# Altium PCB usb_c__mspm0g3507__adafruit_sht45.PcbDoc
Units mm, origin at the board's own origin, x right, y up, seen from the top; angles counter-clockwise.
Board outline 92 x 60 mm, 2 copper layers (Top, Bottom), stack 0 mm thick; 37 components, 33 nets, 186 pads, 47 vias.
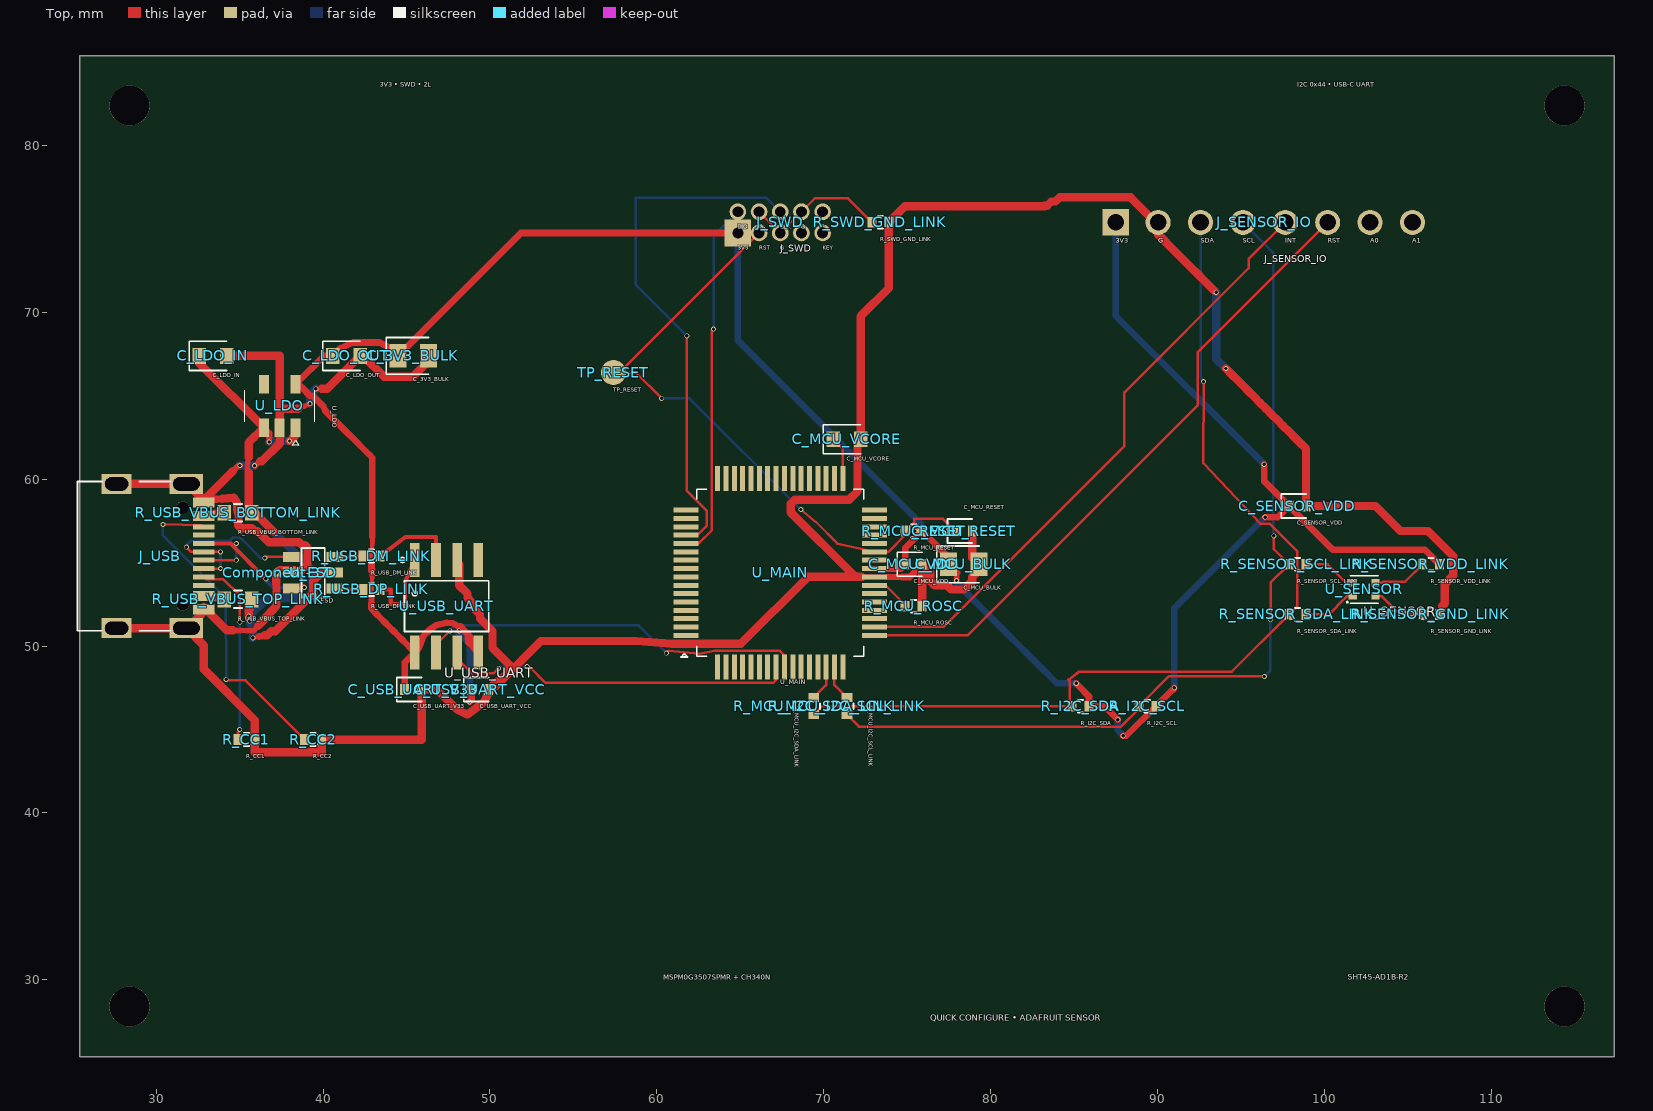
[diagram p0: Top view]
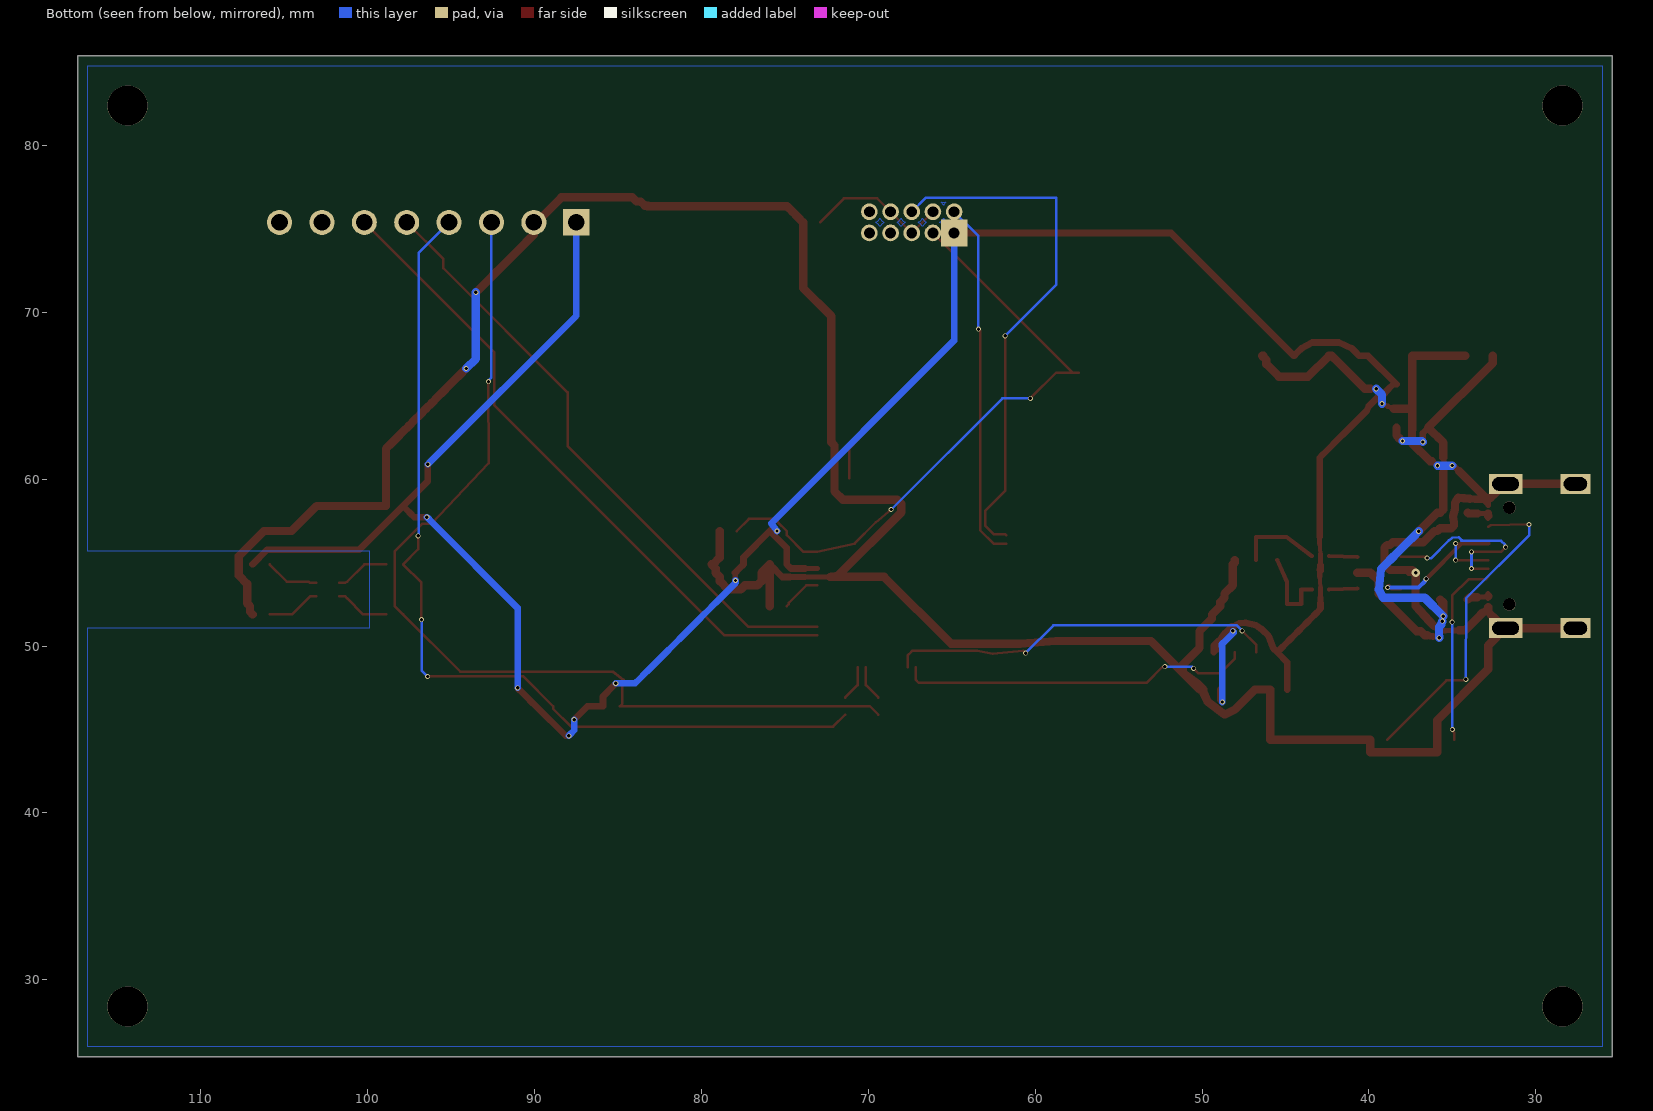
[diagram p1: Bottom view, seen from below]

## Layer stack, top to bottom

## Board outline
25.4,85.4 117.4,85.4 117.4,25.4 25.4,25.4

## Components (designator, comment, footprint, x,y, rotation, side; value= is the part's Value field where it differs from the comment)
C_3V3_BULK "" TSCIRCUIT-2.8500x1.4000mm 45.4,67.4 r0 top
C_LDO_IN "" TSCIRCUIT-2.4500x0.9500mm 33.4,67.4 r0 top
C_LDO_OUT "" TSCIRCUIT-2.4500x0.9500mm 41.4,67.4 r0 top
C_MCU_BULK "" TSCIRCUIT-2.8500x1.4000mm 78.4,54.9 r0 top
C_MCU_RESET "" TSCIRCUIT-1.5600x0.6400mm 78.4,56.9 r0 top
C_MCU_VCORE "" TSCIRCUIT-2.4500x0.9500mm 71.4,62.4 r0 top
C_MCU_VDD "" TSCIRCUIT-1.5600x0.6400mm 75.4,54.9 r0 top
C_SENSOR_VDD "" TSCIRCUIT-1.5600x0.6400mm 98.4,58.4 r0 top
C_USB_UART_V33 "" TSCIRCUIT-1.5600x0.6400mm 45.4,47.4 r0 top
C_USB_UART_VCC "" TSCIRCUIT-1.5600x0.6400mm 49.4,47.4 r0 top
Component-37 "" TSCIRCUIT-0.5000x0.5000mm 37.2,54.4 r0 top
J_SENSOR_IO "" TSCIRCUIT-19.2800x1.5000mm 96.4,75.4 r0 top
J_SWD "" TSCIRCUIT-6.0800x2.2700mm 67.4,75.4 r0 top
J_USB "" TSCIRCUIT-6.7732x9.8502mm 30.113,55.4 r90 top
R_CC1 "" TSCIRCUIT-1.5600x0.6400mm 35.4,44.4 r0 top
R_CC2 "" TSCIRCUIT-1.5600x0.6400mm 39.4,44.4 r0 top
R_I2C_SCL "" TSCIRCUIT-1.5600x0.6400mm 89.4,46.4 r0 top
R_I2C_SDA "" TSCIRCUIT-1.5600x0.6400mm 85.4,46.4 r0 top
R_MCU_I2C_SCL_LINK "" TSCIRCUIT-0.6400x1.5600mm 71.4,46.4 r270 top
R_MCU_I2C_SDA_LINK "" TSCIRCUIT-0.6400x1.5600mm 69.4,46.4 r270 top
R_MCU_RESET "" TSCIRCUIT-1.5600x0.6400mm 75.4,56.9 r0 top
R_MCU_ROSC "" TSCIRCUIT-1.5600x0.6400mm 75.4,52.4 r0 top
R_SENSOR_GND_LINK "" TSCIRCUIT-1.5600x0.6400mm 106.4,51.9 r0 top
R_SENSOR_SCL_LINK "" TSCIRCUIT-1.5600x0.6400mm 98.4,54.9 r0 top
R_SENSOR_SDA_LINK "" TSCIRCUIT-1.5600x0.6400mm 98.4,51.9 r0 top
R_SENSOR_VDD_LINK "" TSCIRCUIT-1.5600x0.6400mm 106.4,54.9 r0 top
R_SWD_GND_LINK "" TSCIRCUIT-1.5600x0.6400mm 73.4,75.4 r0 top
R_USB_DM_LINK "" TSCIRCUIT-1.5600x0.6400mm 42.9,55.4 r0 top
R_USB_DP_LINK "" TSCIRCUIT-1.5600x0.6400mm 42.9,53.4 r0 top
R_USB_VBUS_BOTTOM_LINK "" TSCIRCUIT-2.4500x0.9500mm 34.9,58 r0 top
R_USB_VBUS_TOP_LINK "" TSCIRCUIT-2.4500x0.9500mm 34.9,52.8 r0 top
TP_RESET "" TSCIRCUIT-1.5000x1.5000mm 57.4,66.4 r0 top
U_ESD "" TSCIRCUIT-3.6000x2.5000mm 39.4,54.4 r0 top
U_LDO "" TSCIRCUIT-2.5000x3.7000mm 37.4,64.4 r270 top
U_MAIN "" TSCIRCUIT-12.8000x12.8000mm 67.4,54.4 r0 top
U_SENSOR "" TSCIRCUIT-1.8598x1.2201mm 102.4,53.4 r0 top
U_USB_UART "" TSCIRCUIT-4.3840x7.5712mm 47.4,52.4 r0 top

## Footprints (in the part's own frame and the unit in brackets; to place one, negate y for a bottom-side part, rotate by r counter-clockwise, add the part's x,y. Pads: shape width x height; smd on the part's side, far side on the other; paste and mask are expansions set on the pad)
TSCIRCUIT-0.5000x0.5000mm [mm]
TSCIRCUIT-0.6400x1.5600mm [mm]
  rect 0.54x0.64 smd: 1(-0.51,0) 2(0.51,0)
  silkscreen extent -0.15,-0.38 0.15,0.38
TSCIRCUIT-1.5000x1.5000mm [mm]
  round 1.5 smd: 1(0,0)
TSCIRCUIT-1.5600x0.6400mm [mm]
  rect 0.54x0.64 smd: 1(-0.51,0) 2(0.51,0)
  silkscreen extent -0.98,-0.72 0.51,0.72
TSCIRCUIT-1.8598x1.2201mm [mm]
  rect 0.505x0.42 smd: 1(-0.677,-0.4) 2(-0.677,0.4) 3(0.677,0.4) 4(0.677,-0.4)
  silkscreen extent -1.05,-0.83 0.83,0.83
TSCIRCUIT-2.4500x0.9500mm [mm]
  rect 0.8x0.95 smd: 1(-0.825,0) 2(0.825,0)
  silkscreen extent -1.42,-0.87 0.82,0.87
TSCIRCUIT-2.5000x3.7000mm [mm]
  rect 1.1x0.6 smd: 1(1.3,0.95) 2(1.3,0) 3(1.3,-0.95) 4(-1.3,-0.95) 5(-1.3,0.95)
  silkscreen extent -0.95,-2.1 2.35,2.1
TSCIRCUIT-2.8500x1.4000mm [mm]
  rect 1.025x1.4 smd: 1(-0.913,0) 2(0.913,0)
  silkscreen extent -1.63,-1.1 0.91,1.1
TSCIRCUIT-3.6000x2.5000mm [mm]
  rect 1x0.6 smd: 1(-1.3,-0.95) 2(-1.3,0) 3(-1.3,0.95) 4(1.3,0.95) 5(1.3,0) 6(1.3,-0.95)
  silkscreen extent -0.7,-1.49 0.7,1.49
TSCIRCUIT-4.3840x7.5712mm [mm]
  rect 0.574x2.036 smd: 1(-1.905,2.768) 2(-0.635,2.768) 3(0.635,2.768) 4(1.905,2.768) 5(1.905,-2.768) 6(0.635,-2.768) 7(-0.635,-2.768) 8(-1.905,-2.768)
  silkscreen extent -2.79,-1.52 2.53,2.92
TSCIRCUIT-6.0800x2.2700mm [mm]
  rect 1.6x1.6 hole 0.65: 1(-2.54,-0.635)
  round 1 hole 0.65: 2(-2.54,0.635) 3(-1.27,0.635) 4(0,0.635) 5(1.27,0.635) 6(2.54,0.635) 7(2.54,-0.635) 8(1.27,-0.635) 9(0,-0.635) 10(-1.27,-0.635)
TSCIRCUIT-6.7732x9.8502mm [mm]
  rect 0.3x1.3 smd: 1(-3.35,-2.737) 2(-3.05,-2.737) 3(-2.55,-2.737) 4(-2.25,-2.737) 5(-1.75,-2.737) 6(-1.25,-2.737) 7(-0.75,-2.737) 8(-0.25,-2.737) 9(0.25,-2.737) 10(0.75,-2.737) 11(1.25,-2.737) 12(1.75,-2.737) 13(2.55,-2.737) 14(2.25,-2.737) 15(3.35,-2.737) 16(3.05,-2.737)
  rect 1.2x2 hole 0.8 slot 1.6 at 90 deg: 17(-4.325,-1.693) 18(4.325,-1.693)
  rect 1.2x1.8 hole 0.8 slot 1.4 at 90 deg: 19(4.325,2.487) 20(-4.325,2.487)
  round 0.75 hole 0.75 unplated: NPTH-1(-2.9,-1.468) NPTH-2(2.9,-1.468)
  silkscreen extent -4.47,-0.75 4.47,4.83
TSCIRCUIT-12.8000x12.8000mm [mm]
  rect 1.5x0.3 smd: 1(-5.65,-3.75) 2(-5.65,-3.25) 3(-5.65,-2.75) 4(-5.65,-2.25) 5(-5.65,-1.75) 6(-5.65,-1.25) 7(-5.65,-0.75) 8(-5.65,-0.25) 9(-5.65,0.25) 10(-5.65,0.75) 11(-5.65,1.25) 12(-5.65,1.75) 13(-5.65,2.25) 14(-5.65,2.75) 15(-5.65,3.25) 16(-5.65,3.75) 33(5.65,3.75) 34(5.65,3.25) 35(5.65,2.75) 36(5.65,2.25) 37(5.65,1.75) 38(5.65,1.25) 39(5.65,0.75) 40(5.65,0.25) 41(5.65,-0.25) 42(5.65,-0.75) 43(5.65,-1.25) 44(5.65,-1.75) 45(5.65,-2.25) 46(5.65,-2.75) 47(5.65,-3.25) 48(5.65,-3.75)
  rect 0.3x1.5 smd: 17(-3.75,5.65) 18(-3.25,5.65) 19(-2.75,5.65) 20(-2.25,5.65) 21(-1.75,5.65) 22(-1.25,5.65) 23(-0.75,5.65) 24(-0.25,5.65) 25(0.25,5.65) 26(0.75,5.65) 27(1.25,5.65) 28(1.75,5.65) 29(2.25,5.65) 30(2.75,5.65) 31(3.25,5.65) 32(3.75,5.65) 49(3.75,-5.65) 50(3.25,-5.65) 51(2.75,-5.65) 52(2.25,-5.65) 53(1.75,-5.65) 54(1.25,-5.65) 55(0.75,-5.65) 56(0.25,-5.65) 57(-0.25,-5.65) 58(-0.75,-5.65) 59(-1.25,-5.65) 60(-1.75,-5.65) 61(-2.25,-5.65) 62(-2.75,-5.65) 63(-3.25,-5.65) 64(-3.75,-5.65)
  silkscreen extent -5.95,-5.05 5,5
TSCIRCUIT-19.2800x1.5000mm [mm]
  rect 1.6x1.6 hole 1: 1(-8.89,0)
  round 1.5 hole 1: 2(-6.35,0) 3(-3.81,0) 4(-1.27,0) 5(1.27,0) 6(3.81,0) 7(6.35,0) 8(8.89,0)

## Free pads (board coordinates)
  round 2.4 hole 2.4 unplated: NPTH-3(28.4,28.4) NPTH-4(114.4,28.4) NPTH-5(28.4,82.4) NPTH-6(114.4,82.4)

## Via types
v1: diameter 0.3, hole 0.2, Top to Bottom, 46 vias
v2: diameter 0.5, hole 0.2, Top to Bottom, 1 vias

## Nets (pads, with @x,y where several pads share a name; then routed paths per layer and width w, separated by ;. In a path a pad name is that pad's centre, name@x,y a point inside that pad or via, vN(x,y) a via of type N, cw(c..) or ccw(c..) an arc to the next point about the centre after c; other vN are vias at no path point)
".J_SWD > .pin2 to .U_MAIN > .pin12": J_SWD.2 U_MAIN.12 | length 21.6
  Top w0.15: U_MAIN.12 62.499,56.15 63.298,56.949 63.298,59.12 63.298,68.898 v1(63.4,69)
  Bottom w0.15: v1(63.4,69) 63.4,69.14 63.4,74.575 J_SWD.2
".J_SWD > .pin4 to .U_MAIN > .pin13": J_SWD.4 U_MAIN.13 | length 31.9
  Top w0.15: U_MAIN.13 61.811,56.711 62.49,56.711 63.008,57.229 63.008,58.102 61.8,59.31 v1(61.8,68.6)
  Bottom w0.15: v1(61.8,68.6) 61.756,68.644 58.745,71.655 58.745,76.868 66.567,76.868 J_SWD.4
".U_MAIN > .pin42 to .R_MCU_ROSC > .pin1": R_MCU_ROSC.1 U_MAIN.42 | length 2.4
  Top w0.15: U_MAIN.42 73.719,53.65 74.769,52.6 74.769,52.521 R_MCU_ROSC.1
GND: C_3V3_BULK.2 C_LDO_IN.2 C_LDO_OUT.2 C_MCU_BULK.2 C_MCU_RESET.2 C_MCU_VCORE.2 C_MCU_VDD.2 C_SENSOR_VDD.2 C_USB_UART_V33.2 C_USB_UART_VCC.2 J_SENSOR_IO.2 J_USB.1 J_USB.2 J_USB.15 J_USB.16 J_USB.17 J_USB.18 J_USB.19 J_USB.20 R_CC1.2 R_CC2.2 R_MCU_ROSC.2 R_SENSOR_GND_LINK.2 R_SWD_GND_LINK.2 U_ESD.2 U_LDO.2 U_MAIN.41 U_USB_UART.3 | length 216.2
  Top w0.275: J_USB.16 J_USB.15@33.202,58.803
  Top w0.3: J_USB.1@32.699,51.9 J_USB.1 J_USB.1@32.849,52.2 ; J_USB.15@32.699,58.9 J_USB.15 ; J_USB.2 J_USB.1@32.995,52.2 ; J_USB.16@32.849,58.6 J_USB.15 ; J_USB.15@32.999,58.9 J_USB.15 ; v1(39.568,65.421) 39.907,65.421 ; U_MAIN.41@73.8,54.15 73.706,54.15 73.612,54.15 73.519,54.15 73.425,54.15 73.331,54.15 73.237,54.15 73.144,54.15 U_MAIN.41 ; U_MAIN.41 72.627,54.15 72.3,54.15 72.55,54.15 U_MAIN.41
  Top w0.312: 38.513,64.225 38.866,64.38 v1(39.219,64.535)
  Top w0.325: J_USB.16 J_USB.16@32.849,58.6 ; J_USB.1@32.994,52.2 J_USB.1@33.186,52.003 ; 35.01,50.936 35.417,50.923 35.823,50.911 36.1,51.21 ; v1(35.89,60.817) 35.911,60.796 v1@35.913,60.796
  Top w0.35: v1@35.913,60.796 36.216,61.092 ; 93.416,71.317 v1(93.528,71.205)
  Top w0.375: 34.578,60.479 34.924,60.825 v1(35.007,60.825) ; 34.603,50.948 35.01,50.936 ; U_MAIN.41@73.8,54.15 74.253,54.15 74.707,54.15
  Top w0.4: 37.2,54.4 U_ESD.2@37.6,54.4 ; 74.707,54.15 75.16,54.15 75.41,54.4 75.66,54.65 C_MCU_VDD.2
  Top w0.45: J_USB.15@33.202,58.803 33.611,58.803 33.958,58.835
  Top w0.475: 71.55,54.15 72.05,54.15 72.3,54.15 72.205,54.15
  Top w0.5: J_USB.20 J_USB.17 ; J_USB.19 J_USB.18 31.874,59.725 32.474,59.125 32.699,58.9 ; 32.699,51.9 32.474,51.675 31.874,51.075 J_USB.17 ; J_USB.1@32.849,52.2 J_USB.2 ; 32.999,58.9 34.578,60.479 ; J_USB.1@33.186,52.003 33.522,51.666 33.522,51.655 34.23,50.948 34.603,50.948 ; 33.958,58.835 34.304,58.868 34.65,58.9 34.837,58.588 34.837,58.212 34.955,57.783 34.9,57.4 34.9,57.233 35.067,57.067 35.733,57.067 35.9,56.9 36.067,56.9 36.733,56.233 38.567,56.233 38.733,56.067 38.9,56.067 39.067,55.9 39.067,54.9 38.733,54.567 37.4,54.567 37.233,54.4 37.2,54.4 37.201,53.902 37.202,53.404 37.203,52.906 37.204,52.408 36.928,52.109 36.652,51.809 36.376,51.51 36.1,51.21 ; C_LDO_IN.2 37.4,67.4 U_LDO.2 ; 36.216,61.092 36.342,61.092 37.4,62.15 37.414,62.686 U_LDO.2 ; 38.513,64.225 37.4,64.225 U_LDO.2 ; 39.907,65.421 40.246,65.421 40.576,65.751 40.906,66.081 41.236,66.41 41.565,66.74 41.895,67.07 C_LDO_OUT.2 42.4,67.4 43.65,66.15 45.4,66.15 46.15,66.9 46.15,67.15 46.4,67.4 C_3V3_BULK.2 ; U_USB_UART.3 48.035,55.015 48.15,54.9 48.15,53.65 48.65,53.15 48.65,52.9 48.9,52.65 48.9,52.4 49.4,51.9 49.4,51.65 50.15,50.9 50.15,49.9 51.15,48.9 51.15,48.4 ; 71.55,54.15 71.05,54.15 70.55,54.15 70.05,54.15 69.55,54.15 69.051,54.15 65.051,50.15 60.9,50.15 58.75,50.306 53.056,50.306 51.15,48.4 ; 72.205,54.15 71.994,54.15 71.947,54.197 71.853,54.197 68.025,58.025 68.025,58.525 68.275,58.775 71.525,58.775 72.025,59.275 72.025,62.025 72.225,62.225 C_MCU_VCORE.2 72.225,62.892 72.225,63.384 72.225,63.876 72.225,64.368 72.225,64.86 72.225,65.352 72.225,65.844 72.225,66.336 72.225,66.828 72.225,67.32 72.225,67.812 72.225,68.303 72.225,68.795 72.225,69.287 72.225,69.779 73.91,71.464 R_SWD_GND_LINK.2 74.232,75.722 74.554,76.044 74.876,76.366 74.951,76.366 75.438,76.366 75.925,76.366 76.413,76.366 76.9,76.366 77.387,76.366 77.875,76.366 78.362,76.366 78.849,76.366 79.337,76.366 79.824,76.366 80.311,76.366 80.799,76.366 81.286,76.366 81.773,76.366 82.261,76.366 82.748,76.366 83.235,76.366 83.202,76.4 83.4,76.4 83.65,76.65 83.9,76.65 84.15,76.9 88.4,76.9 89.9,75.4 J_SENSOR_IO.2 90.05,75.033 90.05,74.667 90.385,74.332 90.72,73.997 91.055,73.662 91.39,73.327 91.725,72.992 92.06,72.657 92.395,72.322 92.73,71.987 93.065,71.652 93.4,71.317 93.416,71.317 ; R_MCU_ROSC.2 C_MCU_VDD.2 75.91,54.89 76.4,54.4 76.4,53.9 76.65,53.65 77.4,53.65 77.65,53.4 78.4,53.4 78.9,53.9 78.9,54.15 79.15,54.4 79.15,54.65 79.4,54.9 C_MCU_BULK.2 78.91,55.303 C_MCU_RESET.2 ; v1(94.107,66.639) 94.45,66.296 94.793,65.953 95.136,65.61 95.479,65.267 95.822,64.924 96.165,64.581 96.508,64.237 96.852,63.894 97.195,63.551 97.538,63.208 97.881,62.865 98.224,62.522 98.567,62.179 98.91,61.836 98.91,61.345 98.91,60.854 98.91,60.363 98.91,59.873 98.91,59.382 98.91,58.891 C_SENSOR_VDD.2 99.41,58.4 99.909,58.4 100.409,58.4 100.908,58.4 101.408,58.4 101.907,58.4 102.407,58.4 102.907,58.4 103.067,58.4 104.567,56.9 106.233,56.9 107.733,55.4 107.733,54.233 107.233,53.733 107.233,52.567 107.067,52.4 107.067,52.067 106.9,51.9 R_SENSOR_GND_LINK.2 ; J_USB.17 32.845,50.035 32.845,48.621 35.91,45.556 R_CC1.2 35.91,43.65 39.91,43.65 R_CC2.2 40.41,44.4 40.91,44.4 45.91,44.4 C_USB_UART_V33.2 46.832,47.4 48.003,46.229 48.65,45.9 49.65,46.65 49.913,47.226 49.913,47.397 C_USB_UART_VCC.2 ; C_USB_UART_VCC.2 50.15,47.4 51.15,48.4 ; C_USB_UART_VCC.2 50.233,47.723 51.15,48.4
  Bottom w0.5: v1(35.007,60.825) 35.015,60.817 v1(35.89,60.817) ; v1(39.219,64.535) 39.219,64.804 39.219,65.072 39.544,65.397 v1(39.568,65.421) ; v1(93.528,71.205) 93.528,67.218 v1(94.107,66.639)
MAIN_RESET: C_MCU_RESET.1 J_SWD.10 R_MCU_RESET.1 TP_RESET.1 U_MAIN.38 | length 38.3
  Top w0.15: v1(60.288,64.85) 60.277,64.861 58.738,66.4 TP_RESET.1 57.765,66.4 J_SWD.10 ; v1(68.634,58.195) 69.555,57.424 70.823,56.15 U_MAIN.38 73.889,55.65 74.889,56.651 R_MCU_RESET.1@74.889,56.899 ; R_MCU_RESET.1 75.442,57.452 75.442,57.636 77.166,57.628 C_MCU_RESET.1
  Bottom w0.15: v1(60.288,64.85) 61.971,64.85 68.557,58.264 v1(68.634,58.195)
MCU_I2C_SCL_LOCAL: R_MCU_I2C_SCL_LINK.1 U_MAIN.50 | length 2.2
  Top w0.15: U_MAIN.50 70.65,47.66 R_MCU_I2C_SCL_LINK.1
MCU_I2C_SDA_LOCAL: R_MCU_I2C_SDA_LINK.1 U_MAIN.51 | length 2.2
  Top w0.15: R_MCU_I2C_SDA_LINK.1 70.15,47.66 U_MAIN.51
MSPM0_VCORE: C_MCU_VCORE.1 U_MAIN.32 | length 2.6
  Top w0.15: C_MCU_VCORE.1 71.15,61.825 U_MAIN.32
SENSOR_ADDR0: J_SENSOR_IO.7
SENSOR_ADDR1: J_SENSOR_IO.8
SENSOR_INT: J_SENSOR_IO.5 U_MAIN.47 | length 36.9
  Top w0.15: U_MAIN.47 77.192,51.15 88.03,61.988 88.031,65.213 95.474,72.651 95.471,73.201 J_SENSOR_IO.5
SENSOR_RESET: J_SENSOR_IO.6 U_MAIN.48 | length 39.3
  Top w0.15: U_MAIN.48 78.62,50.65 92.431,64.465 92.432,67.625 J_SENSOR_IO.6
SENSOR_SCL: J_SENSOR_IO.4 R_I2C_SCL.1 R_MCU_I2C_SCL_LINK.2 R_SENSOR_SCL_LINK.1 | length 55.6
  Top w0.15: R_MCU_I2C_SCL_LINK.2 72.112,45.178 87.819,45.178 88.89,46.249 R_I2C_SCL.1 90.673,48.183 v1(96.416,48.183) ; v1(96.779,51.587) 96.796,51.604 96.796,53.806 R_SENSOR_SCL_LINK.1 96.982,55.808 v1(96.982,56.617)
  Bottom w0.15: J_SENSOR_IO.4 96.953,73.577 96.953,56.656 96.953,56.646 v1(96.982,56.617) ; v1(96.416,48.183) 96.456,48.223 96.779,48.546 v1(96.779,51.587)
SENSOR_SDA: J_SENSOR_IO.3 R_I2C_SDA.1 R_MCU_I2C_SDA_LINK.2 R_SENSOR_SDA_LINK.1 | length 58.6
  Top w0.15: R_MCU_I2C_SDA_LINK.2 69.91,46.4 R_I2C_SDA.1 84.741,46.549 84.741,46.588 84.741,47.895 84.675,47.975 85.312,48.467 94.457,48.467 R_SENSOR_SDA_LINK.1 98.4,52.41 98.4,55.68 96.73,57.35 96.373,57.345 96.171,57.337 92.765,60.964 v1(92.772,65.85)
  Bottom w0.15: J_SENSOR_IO.3 92.59,66.104 92.734,65.96 92.734,65.881 v1(92.772,65.85)
SHT_GND_LOCAL: R_SENSOR_GND_LINK.1 U_SENSOR.4 | length 3.3
  Top w0.15: U_SENSOR.4 103.44,53 103.551,52.893 104.544,51.9 R_SENSOR_GND_LINK.1
SHT_SCL_LOCAL: R_SENSOR_SCL_LINK.2 U_SENSOR.2 | length 3.3
  Top w0.15: R_SENSOR_SCL_LINK.2 100.201,54.9 101.232,53.868 101.36,53.8 U_SENSOR.2
SHT_SDA_LOCAL: R_SENSOR_SDA_LINK.2 U_SENSOR.1 | length 3.3
  Top w0.15: R_SENSOR_SDA_LINK.2 100.281,51.9 101.256,52.875 101.36,53 U_SENSOR.1
SHT_VDD_LOCAL: R_SENSOR_VDD_LINK.1 U_SENSOR.3 | length 3.3
  Top w0.15: U_SENSOR.3 103.44,53.8 103.496,53.801 103.553,53.858 104.848,53.858 R_SENSOR_VDD_LINK.1
swd-ground-1-to-2: J_SWD.3 J_SWD.5 J_SWD.9 R_SWD_GND_LINK.1 | length 8.8
  Top w0.15: J_SWD.3 J_SWD.9 J_SWD.5 69.481,76.846 71.471,76.846 71.471,76.819 R_SWD_GND_LINK.1
UART_MSP_RX: U_MAIN.57 U_USB_UART.6 | length 21.3
  Top w0.15: U_USB_UART.6 48.035,49.252 48.913,48.373 50.202,48.373 v1(50.502,48.673) ; v1(52.23,48.77) 52.261,48.739 52.386,48.739 53.309,47.815 66.991,47.808 67.15,47.975 U_MAIN.57
  Bottom w0.15: v1(50.502,48.673) 50.507,48.678 50.52,48.678 50.612,48.77 v1(52.23,48.77)
UART_MSP_TX: U_MAIN.56 U_USB_UART.7 | length 23.4
  Top w0.15: U_USB_UART.7 46.765,50.089 v1(47.6,50.922) ; v1(60.574,49.581) 60.715,49.722 62.558,49.552 63.471,49.722 67.369,49.722 67.431,49.659 67.65,49.441 U_MAIN.56
  Bottom w0.15: v1(47.6,50.922) 47.674,50.998 47.674,51 47.915,51.241 48.027,51.255 58.914,51.241 v1(60.574,49.581)
usb-dm-device: R_USB_DM_LINK.1 U_ESD.4 | length 1.7
  Top w0.25: U_ESD.4 R_USB_DM_LINK.1
usb-dm-port-tie: J_USB.7 J_USB.9 U_ESD.3 | length 11.4
  Top w0.15: v1(31.806,55.929) 32.085,55.65 32.601,55.65 J_USB.9 v1(33.85,55.65) ; J_USB.7 v1(33.85,54.65) ; v1(36.508,55.282) 36.576,55.35 36.6,55.35 U_ESD.3
  Bottom w0.15: v1(31.806,55.929) 31.847,55.97 31.847,56.08 32.075,56.309 34.46,56.31 34.413,56.339 34.602,56.515 35.009,56.494 35.202,56.348 36.257,55.282 v1(36.508,55.282) ; v1(33.85,54.65) v1(33.85,55.65)
usb-dm-uart: R_USB_DM_LINK.2 U_USB_UART.2 | length 5.1
  Top w0.25: R_USB_DM_LINK.2 44.95,56.55 46.765,56.55 U_USB_UART.2
usb-dp-device: R_USB_DP_LINK.1 U_ESD.6 | length 1.7
  Top w0.25: U_ESD.6 R_USB_DP_LINK.1
usb-dp-port-tie: J_USB.8 J_USB.10 U_ESD.1 | length 12.9
  Top w0.15: J_USB.8 v1(34.8,55.15) ; J_USB.10 v1(34.8,56.15)
  Top w0.25: J_USB.10 34.451,56.15 v1(36.565,54.036) ; U_ESD.1 38.65,53.45 38.791,53.591 38.834,53.591 v1(38.871,53.513)
  Bottom w0.15: v1(34.8,55.15) v1(34.8,56.15)
  Bottom w0.25: v1(36.565,54.036) 36.64,53.961 36.64,53.889 37.02,53.509 v1(38.871,53.513)
usb-dp-uart: R_USB_DP_LINK.2 U_USB_UART.1 | length 5.1
  Top w0.25: R_USB_DP_LINK.2 44.05,53.4 44.05,52.53 44.9,52.53 44.9,53.85 U_USB_UART.1
USB_CC1: J_USB.6 R_CC1.1 | length 11.3
  Top w0.15: J_USB.6 32.974,54.025 34.012,54.025 35.007,53.03 v1(35.007,51.44) ; R_CC1.1 34.89,44.822 34.945,44.877 34.945,44.945 v1(35,45)
  Bottom w0.15: v1(35,45) 35,51.244 35.004,51.247 35.004,51.437 v1(35.007,51.44)
USB_CC2: J_USB.12 R_CC2.1 | length 19.5
  Top w0.15: v1(30.406,57.294) 32.684,57.242 J_USB.12 ; v1(34.19,48.01) 34.21,47.941 34.357,47.941 35.349,47.941 R_CC2.1
  Bottom w0.15: v1(30.406,57.294) 30.384,57.272 30.384,57.166 30.384,56.666 34.166,52.884 v1(34.19,48.01)
USB_VBUS_BOTTOM_LOCAL: J_USB.13 J_USB.14 R_USB_VBUS_BOTTOM_LINK.1 | length 1.5
  Top w0.3: J_USB.14 J_USB.14@32.849,57.8 ; J_USB.13 32.927,57.95 33.005,57.95 33.083,57.95 33.161,57.95 33.239,57.95 33.317,57.95 33.394,57.95 33.472,57.95 33.499,57.95
  Top w0.475: J_USB.13@32.849,57.8 J_USB.13 ; 33.499,57.95 R_USB_VBUS_BOTTOM_LINK.1@33.762,57.95
  Top w0.5: R_USB_VBUS_BOTTOM_LINK.1@33.762,57.95 34.025,57.95 R_USB_VBUS_BOTTOM_LINK.1
USB_VBUS_TOP_LOCAL: J_USB.3 J_USB.4 R_USB_VBUS_TOP_LINK.1 | length 1.6
  Top w0.3: J_USB.4 32.849,53 J_USB.3 32.945,52.958 33.032,52.939 33.499,52.939
  Top w0.5: 33.499,52.939 33.675,52.939 33.936,52.939 R_USB_VBUS_TOP_LINK.1
VBUS5: C_LDO_IN.1 R_USB_VBUS_BOTTOM_LINK.2 R_USB_VBUS_TOP_LINK.2 U_ESD.5 U_LDO.1 U_LDO.3 | length 36
  Top w0.275: v1(35.6,51.5) 35.602,51.778 35.601,52.226 ; v1(35.792,50.497) 36.151,50.566
  Top w0.325: 35.537,61.305 35.462,60.869 35.462,60.4 35.538,60.411 ; v1(36.763,62.238) 36.781,62.494
  Top w0.375: U_LDO.3 36.781,62.769
  Top w0.4: 36.781,62.494 36.781,62.769
  Top w0.425: 36.151,50.566 36.51,50.636
  Top w0.45: v1(37.981,62.292) 38.121,62.432 38.151,62.432
  Top w0.5: C_LDO_IN.1 32.575,66.975 U_LDO.3 36.145,62.799 35.84,62.499 35.535,62.198 35.536,61.752 35.537,61.305 ; 35.538,60.411 35.538,58.187 R_USB_VBUS_BOTTOM_LINK.2 35.895,58 36.174,57.721 36.453,57.442 36.733,57.162 37.012,56.883 v1(37.017,56.878) ; v1(35.546,51.795) 35.546,52.621 R_USB_VBUS_TOP_LINK.2 35.6,52.675 35.601,52.226 ; 36.51,50.636 36.496,50.65 36.65,50.65 36.9,50.9 37.15,50.9 39.4,53.15 39.4,53.9 39.9,54.4 U_ESD.5 ; 38.151,62.432 38.35,62.631 U_LDO.1
  Bottom w0.5: v1(35.546,51.795) 36.651,52.9 39.15,52.9 39.4,53.4 39.275,54.627 38.952,54.948 38.63,55.27 38.307,55.591 37.985,55.913 37.662,56.235 37.34,56.556 v1(37.017,56.878) ; v1(35.6,51.5) 35.653,51.347 35.653,51.288 35.796,51.145 35.794,50.821 v1(35.792,50.497) ; v1(36.763,62.238) 36.817,62.292 v1(37.981,62.292)
VCC_3V3: C_3V3_BULK.1 C_LDO_OUT.1 C_MCU_BULK.1 C_MCU_VDD.1 C_SENSOR_VDD.1 C_USB_UART_V33.1 C_USB_UART_VCC.1 J_SENSOR_IO.1 J_SWD.1 R_I2C_SCL.2 R_I2C_SDA.2 R_MCU_RESET.2 R_SENSOR_VDD_LINK.2 U_LDO.5 U_MAIN.40 U_USB_UART.5 U_USB_UART.8 | length 161.7
  Top w0.25: 42.9,53.525 42.923,53.859 42.946,54.193 ; 42.9,55.525 42.923,55.845 42.946,56.166
  Top w0.275: 42.9,52.9 42.9,53.212 42.9,53.525 ; 42.9,54.858 42.9,55.192 42.9,55.525
  Top w0.3: 42.946,56.166 42.946,56.561 ; v1(48.152,50.915) 48.45,50.9 48.6,50.75 ; U_MAIN.40 73.15,54.65 73.25,54.65 73.35,54.65 73.45,54.65 73.55,54.65 73.65,54.65 73.75,54.65 U_MAIN.40@73.8,54.65
  Top w0.312: 42.946,54.193 42.946,54.587
  Top w0.325: 48.6,50.75 48.658,50.485 ; v1(77.966,53.94) 77.98,54.167 C_MCU_BULK.1@77.993,54.394
  Top w0.337: v1(48.783,46.652) v1@48.8,46.687
  Top w0.375: 48.658,50.485 48.716,50.221 ; v1@48.8,46.687 48.89,46.777
  Top w0.387: 42.9,52.587 42.9,52.9
  Top w0.4: 42.9,52.587 42.9,52.275 42.946,52.22 42.946,52.181 43.201,51.926 43.456,51.671 43.711,51.416 43.966,51.161 44.221,50.906 44.475,50.652 44.73,50.397 44.985,50.142 45.24,49.887 U_USB_UART.8 ; 42.9,54.858 42.9,54.525 42.946,54.587 ; 42.946,56.561 42.946,56.955 42.946,57.35 42.946,57.744 42.946,58.139 42.946,58.534 42.946,58.928 42.946,59.323 42.946,59.718 42.946,60.112 42.946,60.507 42.946,60.901 42.946,61.296 42.824,61.418 42.556,61.686 42.289,61.953 42.021,62.221 41.754,62.489 41.486,62.756 41.218,63.024 40.951,63.291 40.683,63.559 40.416,63.827 40.148,64.094 40,64.4 39.4,65 39.2,65 38.81,65.432 38.542,65.7 U_LDO.5 40.05,67.4 C_LDO_OUT.1 40.795,67.622 41.016,67.843 41.8,68.2 43.4,68.2 44.047,67.841 44.267,67.62 C_3V3_BULK.1 51.853,74.765 J_SWD.1 ; C_USB_UART_V33.1 44.89,49.027 U_USB_UART.8 ; 48.716,50.221 48.912,50.025 49.109,49.828 U_USB_UART.5 49.305,50.013 49.076,50.242 48.847,50.471 48.6,50.8 48.2,51.2 48.16,51.158 47.775,51.375 47.4,51.4 46.774,51.261 46.4,51 46,50.6 45.728,49.865 U_USB_UART.8 ; 48.89,46.777 48.89,47.089 C_USB_UART_VCC.1 ; U_MAIN.40@73.8,54.65 73.85,54.65 74.64,54.65 C_MCU_VDD.1 74.89,55.88 R_MCU_RESET.2 ; v1(75.475,56.9) 75.822,56.988 R_MCU_RESET.2 ; C_MCU_BULK.1@77.993,54.394 77.74,54.647 C_MCU_BULK.1 77.488,55.323 R_MCU_RESET.2 ; v1(85.141,47.775) 85.261,47.655 85.261,47.631 85.477,47.415 85.694,47.198 85.91,46.982 85.91,46.691 R_I2C_SDA.2 86.839,46.4 87.591,45.648 87.591,45.631 v1(87.63,45.592) ; v1(87.951,44.628) 88.138,44.628 R_I2C_SCL.2 89.925,46.4 90.184,46.659 90.443,46.918 90.702,47.177 90.961,47.436 v1(91.023,47.498) ; v1(96.402,60.901) 96.402,59.888 C_SENSOR_VDD.1 ; v1(96.467,57.733) 96.842,57.73 97.217,57.727 97.442,57.952 97.666,58.176 C_SENSOR_VDD.1 ; R_SENSOR_VDD_LINK.2 106.026,55.784 100.506,55.784 C_SENSOR_VDD.1
  Bottom w0.325: v1@48.106,50.86 v1(48.152,50.915)
  Bottom w0.4: v1@48.106,50.86 48.106,50.819 48.337,50.588 48.569,50.357 48.8,50.125 48.798,49.739 48.796,49.353 48.794,48.967 48.792,48.582 48.79,48.196 48.788,47.81 48.786,47.424 48.784,47.038 v1(48.783,46.652) ; J_SWD.1 64.86,68.322 75.822,57.361 v1(75.475,56.9) ; v1(77.966,53.94) 77.958,53.863 77.958,53.794 78.232,53.52 78.505,53.247 78.779,52.973 79.052,52.699 79.326,52.426 79.599,52.152 79.873,51.879 80.147,51.605 80.42,51.332 80.694,51.058 80.967,50.784 81.241,50.511 81.515,50.237 81.788,49.964 82.062,49.69 82.335,49.417 82.609,49.143 82.882,48.869 83.156,48.596 83.43,48.322 83.703,48.049 83.977,47.775 84.365,47.775 84.753,47.775 v1(85.141,47.775) ; J_SENSOR_IO.1 87.51,69.794 96.274,61.03 v1(96.402,60.901) ; v1(87.63,45.592) 87.63,44.959 87.889,44.7 87.889,44.69 v1(87.951,44.628) ; v1(91.023,47.498) 91.023,47.897 91.023,48.297 91.023,48.696 91.023,49.095 91.023,49.494 91.023,49.894 91.023,50.293 91.023,50.692 91.023,51.091 91.023,51.491 91.023,51.89 91.023,52.289 91.294,52.56 91.564,52.83 91.835,53.101 92.105,53.372 92.376,53.642 92.646,53.913 92.917,54.183 93.188,54.454 93.458,54.724 93.729,54.995 93.999,55.266 94.27,55.536 94.541,55.807 94.811,56.077 95.082,56.348 95.352,56.619 95.623,56.889 95.893,57.16 96.164,57.43 96.435,57.701 v1(96.467,57.733)
pads on no net: J_SWD.6 J_SWD.7 J_SWD.8 J_USB.5 J_USB.11 J_USB.NPTH-1 J_USB.NPTH-2 U_LDO.4 U_MAIN.1 U_MAIN.2 U_MAIN.3 U_MAIN.4 U_MAIN.5 U_MAIN.6 U_MAIN.7 U_MAIN.8 U_MAIN.9 U_MAIN.10 U_MAIN.11 U_MAIN.14 U_MAIN.15 U_MAIN.16 U_MAIN.17 U_MAIN.18 U_MAIN.19 U_MAIN.20 U_MAIN.21 U_MAIN.22 U_MAIN.23 U_MAIN.24 U_MAIN.25 U_MAIN.26 U_MAIN.27 U_MAIN.28 U_MAIN.29 U_MAIN.30 U_MAIN.31 U_MAIN.33 U_MAIN.34 U_MAIN.35 U_MAIN.36 U_MAIN.37 U_MAIN.39 U_MAIN.43 U_MAIN.44 U_MAIN.45 U_MAIN.46 U_MAIN.49 U_MAIN.52 U_MAIN.53 U_MAIN.54 U_MAIN.55 U_MAIN.58 U_MAIN.59 U_MAIN.60 U_MAIN.61 U_MAIN.62 U_MAIN.63 U_MAIN.64 U_USB_UART.4
copper on no net:
  other v2: 37.2,54.4

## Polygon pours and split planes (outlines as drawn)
GND on Bottom (solid): 116.8,84.8 26,84.8 26,26 116.8,26 116.8,51.1 100.2,51.1 99.9,51.1 99.9,51.4 99.9,55.1 99.9,55.7 100.5,55.7 116.8,55.7
GND on Bottom (solid): 65.633,76.593 65.357,76.593 65.39,76.565 65.484,76.452 65.495,76.43 65.506,76.452 65.6,76.565
GND on Bottom (solid): 65.495,75.64 65.484,75.618 65.399,75.515 65.591,75.515 65.506,75.618
GND on Bottom (solid): 65.61,75.496 65.61,75.304 65.713,75.389 65.735,75.4 65.713,75.411
GND on Bottom (solid): 69.305,75.64 69.294,75.618 69.2,75.505 69.087,75.411 69.065,75.4 69.087,75.389 69.2,75.295 69.294,75.182 69.305,75.16 69.316,75.182 69.41,75.295 69.523,75.389 69.545,75.4 69.523,75.411 69.41,75.505 69.316,75.618
GND on Bottom (solid): 68.035,75.64 68.024,75.618 67.93,75.505 67.817,75.411 67.795,75.4 67.817,75.389 67.93,75.295 68.024,75.182 68.035,75.16 68.046,75.182 68.14,75.295 68.253,75.389 68.275,75.4 68.253,75.411 68.14,75.505 68.046,75.618
GND on Bottom (solid): 66.765,75.64 66.754,75.618 66.66,75.505 66.547,75.411 66.525,75.4 66.547,75.389 66.66,75.295 66.754,75.182 66.765,75.16 66.776,75.182 66.87,75.295 66.983,75.389 67.005,75.4 66.983,75.411 66.87,75.505 66.776,75.618

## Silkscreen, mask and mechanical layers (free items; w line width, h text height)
Top Overlay:
  text "3V3 • SWD • 2L" at 43.4,83.4 h0.48
  text "I2C 0x44 • USB-C UART" at 98.4,83.4 h0.5
  text "MSPM0G3507SPMR + CH340N" at 60.4,29.9 h0.52
  text "SHT45-AD1B-R2" at 101.4,29.9 h0.55
  text "QUICK CONFIGURE • ADAFRUIT SENSOR" at 76.4,27.4 h0.65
